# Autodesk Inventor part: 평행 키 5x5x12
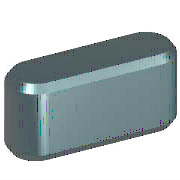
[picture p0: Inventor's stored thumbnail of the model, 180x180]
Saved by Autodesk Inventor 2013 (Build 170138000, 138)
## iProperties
IsCustomPart: 1
Created: 2012-02
Part Number: 평행 키 5x5x12
Material: 강철, 연강
Description: 평행 키
Document SubType Name: Modeling
Standard: JIS B 1301
Designer: mdu-01
Standards Organization: JIS
Language: ko-KR
Size Designation: 5x5x12
Categories: <MemberInstance><Categories><Category DisplayName="샤프트 부품" InternalName="7f7aeb1f-a693-4053-b835-cee3144e0d98" Mnemonic="SHFT"><Category DisplayName="키" Interna
Density: 1 g/cm^3
Author: mdu-01
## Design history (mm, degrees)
workplane "Work Plane1"
workplane "Work Plane2"
sketch "스케치1"
  geometry: L1 (2.5, 2.5)-(9.5, 2.5); L2 (9.5, -2.5)-(2.5, -2.5); L3 (0, 9.4)-(0, -7.4) reference; L4 (-5, 0)-(30, 0) reference; L5 (12, 0)-(12, 7); A1 r 2.5 centre (2.5, 0) between (2.5, 2.5) and (2.5, -2.5); A2 r 2.5 centre (9.5, 0) between (9.5, -2.5) and (9.5, 2.5)
  constraints: 6 end point, 5 point on circle, 4 tangent, 3 point on line, 2 centre point, 1 horizontal, 1 parallel, 1 perpendicular
  dimensions: "d0" = 2.5 radius of A1 (= 0.5 x PB); "d13" = 2.5 radius of A2 (= 0.5 x PB); "d14" = 12 distance between parallel lines of L5 L3 (= NLG)
extrude "본체1" new body sketch "스케치1" taper "d3" = 0 deg; stored distance "d4" = 10
workplane "Work Plane3"
body "Solid1"
chamfer "모따기1" distance "d8" = 0.4 (= PHH); stored, may be unused: second distance "d9" = 0.4 (= PHH), angle "d15" = 45 deg
other parameters: "d1" = -3 (= -PNT), "d2" = 2 (= PH - PNT), "NLG" = 12 [user parameter; used in 3 equation terms], "PB" = 5 [user parameter; used in 2 equation terms], "PNT" = 3 [user parameter; used in 2 equation terms], "PH" = 5 [user parameter; used in 1 equation term], "PHH" = 0.4 [user parameter; used in 2 equation terms], "d10" = 0, "d16" = 0, "d17" = 0, "d18" = 0, "WDMIN" = 12 [user parameter], "PLB2" = 12 (= NLG) [user parameter], "WDMAX" = 17 [user parameter], "PLB1" = 12 (= NLG) [user parameter], "RR" = 0.16 [user parameter], "PUEB" = 2.3 [user parameter]
